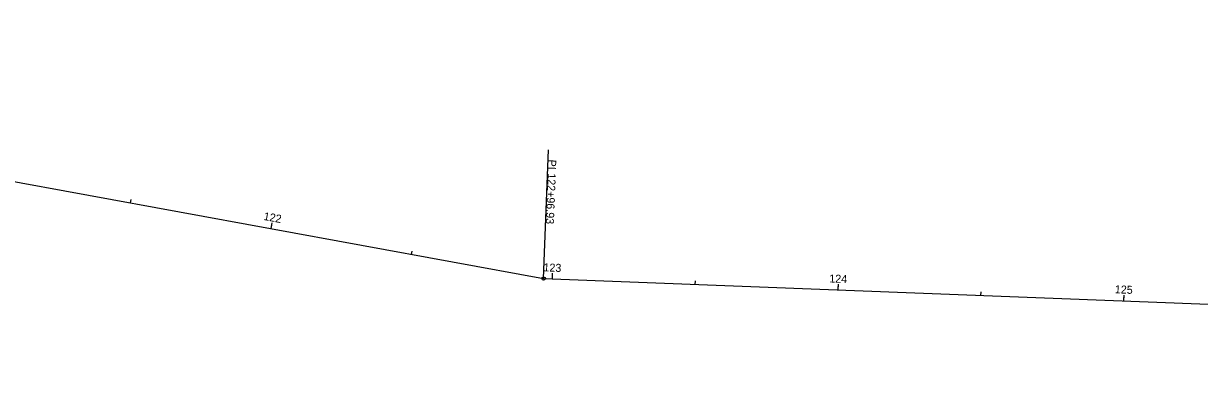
# Model space of a CAD drawing. Extents: x 2003596 to 2006888, y 572582 to 572983.
# Drawn here: x 2004849.6 to 2005260.9, y 572597.3 to 572724.5 of the extents above; entities that cross this region are included whole.
import ezdxf

# ---------------------------------------------------------------- set-up
doc = ezdxf.new("R2010")
doc.units = 0
for name, color, linetype in [('DR_X_Ditch', 7, 'Continuous'), ('PM_X_Surveyed_Line', 7, 'Continuous'), ('PV_X_COP', 7, 'Continuous'), ('RD_X_Fence', 7, 'Continuous'), ('SV_X_Top_of_Bank', 7, 'Continuous'), ('UT_X_Water_Cells', 7, 'Continuous'), ('VG_X_Tree_Line_Lt', 7, 'Continuous')]:
    doc.layers.add(name, color=color, linetype=linetype)

msp = doc.modelspace()

# ---------------------------------------------------------------- linework, layer by layer
at = {"layer": 'DR_X_Ditch'}
for p, q in [((2004886.96, 572661.81), (2004887.18, 572662.99)), ((2004936.14, 572652.8), (2004936.5, 572654.76)), ((2004985.32, 572643.78), (2004985.54, 572644.96)), ((2005034.55, 572635.2), (2005034.63, 572637.2)), ((2005084.51, 572633.28), (2005084.56, 572634.48)), ((2005134.47, 572631.37), (2005134.55, 572633.37)), ((2005184.44, 572629.45), (2005184.48, 572630.65)), ((2005234.4, 572627.53), (2005234.48, 572629.53))]:
    msp.add_line(p, q, dxfattribs=at)
at = {"layer": 'PM_X_Surveyed_Line'}
for p, q in [((2004545, 572724.5), (2005031.48, 572635.32)), ((2005031.48, 572635.32), (2006023.62, 572597.25))]:
    msp.add_line(p, q, dxfattribs=at)
at = {"layer": 'PV_X_COP'}
msp.add_line((2005031.48, 572635.32), (2005033.2, 572680.29), dxfattribs=at)
msp.add_circle((2005031.48, 572635.32), 0.6, dxfattribs=at)
at = {"layer": 'RD_X_Fence'}
for p, q in [((2004936.14, 572652.8), (2004936.36, 572653.98)), ((2005034.55, 572635.2), (2005034.59, 572636.4)), ((2005134.47, 572631.37), (2005134.52, 572632.57)), ((2005234.4, 572627.53), (2005234.48, 572629.53))]:
    msp.add_line(p, q, dxfattribs=at)
at = {"layer": 'SV_X_Top_of_Bank'}
msp.add_line((2005031.48, 572635.32), (2005033.2, 572680.29), dxfattribs=at)
msp.add_circle((2005031.48, 572635.32), 0.6, dxfattribs=at)
at = {"layer": 'UT_X_Water_Cells'}
msp.add_line((2005234.4, 572627.53), (2005234.45, 572628.73), dxfattribs=at)
at = {"layer": 'VG_X_Tree_Line_Lt'}
msp.add_line((2005031.48, 572635.32), (2005033.2, 572680.29), dxfattribs=at)
msp.add_circle((2005031.48, 572635.32), 0.6, dxfattribs=at)

# ---------------------------------------------------------------- texts
at = {"layer": 'DR_X_Ditch'}
for s, rotation, p in [('122', 349.6122, (2004933.37, 572655.85)), ('123', 357.8026, (2005031.38, 572637.87)), ('124', 357.8026, (2005131.33, 572633.99)), ('125', 357.8026, (2005231.21, 572630.2))]:
    msp.add_text(s, height=2.8, rotation=rotation, dxfattribs=at).set_placement(p)
at = {"layer": 'PV_X_COP'}
for s, p in [('PI', (2005033.12, 572676.98)), ('122+96.93', (2005032.94, 572672.2))]:
    msp.add_text(s, height=2.8, rotation=267.8026, dxfattribs=at).set_placement(p)
at = {"layer": 'RD_X_Fence'}
msp.add_text('125', height=2.8, rotation=357.8026, dxfattribs=at).set_placement((2005231.21, 572630.2))
at = {"layer": 'SV_X_Top_of_Bank'}
for s, p in [('PI', (2005033.12, 572676.98)), ('122+96.93', (2005032.94, 572672.2))]:
    msp.add_text(s, height=2.8, rotation=267.8026, dxfattribs=at).set_placement(p)
at = {"layer": 'VG_X_Tree_Line_Lt'}
for s, p in [('PI', (2005033.12, 572676.98)), ('122+96.93', (2005032.94, 572672.2))]:
    msp.add_text(s, height=2.8, rotation=267.8026, dxfattribs=at).set_placement(p)

doc.saveas('drawing.dxf')
